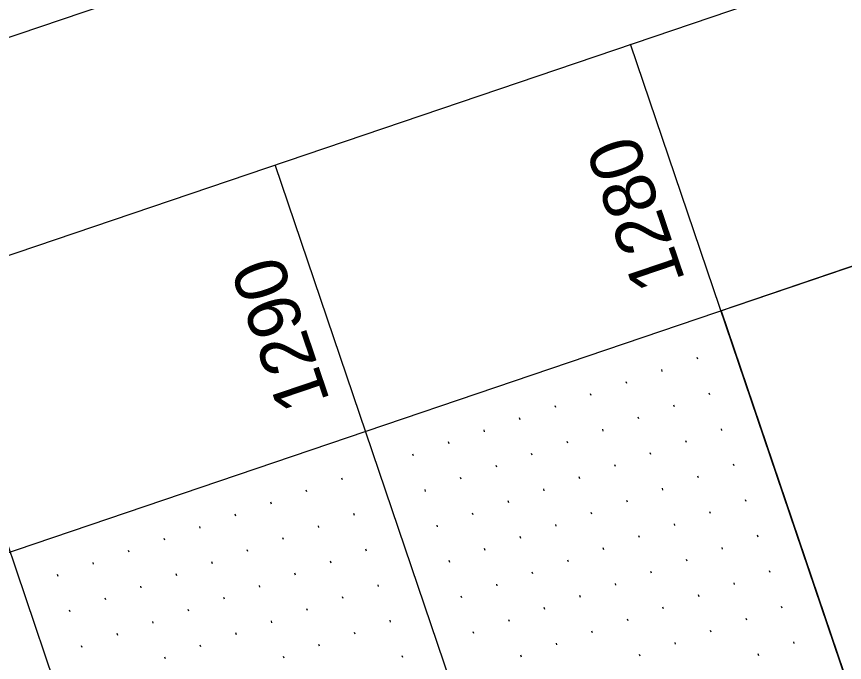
# Model space of a CAD drawing. Extents: x 2150800 to 2152547, y 141860 to 143950.
# Drawn here: x 2151679 to 2151789.3, y 143760 to 143846.1 of the extents above; entities that cross this region are included whole.
import ezdxf

# ---------------------------------------------------------------- set-up
doc = ezdxf.new("R2010")
doc.units = 0
for name, color, linetype in [('SHT_Plan_Profile_Sheet_Elev_Txt', 7, 'Continuous'), ('SHT_Plot_Shape_Half', 7, 'Continuous'), ('SHT_Profile_Grid_Major', 7, 'Continuous'), ('SHT_Profile_Grid_Minor', 7, 'Continuous'), ('SHT_Sheet_Border', 7, 'Continuous')]:
    doc.layers.add(name, color=color, linetype=linetype)

msp = doc.modelspace()

# ---------------------------------------------------------------- linework, layer by layer
at = {"layer": 'SHT_Plot_Shape_Half'}
msp.add_lwpolyline([(2151391.39, 141950.92), (2150845.24, 143560.8), (2151886.93, 143914.19), (2152433.08, 142304.31)], close=True, dxfattribs=at)
at = {"layer": 'SHT_Profile_Grid_Major'}
for p, q in [((2152266.81, 142350.86), (2151760.82, 143842.37)), ((2152219.46, 142334.8), (2151713.47, 143826.31)), ((2152172.11, 142318.73), (2151666.12, 143810.24))]:
    msp.add_line(p, q, dxfattribs=at)
at = {"layer": 'SHT_Profile_Grid_Minor'}
for p, q in [((2151769.78, 143800.4), (2151769.7, 143800.63)), ((2151765.04, 143798.79), (2151764.96, 143799.03)), ((2151760.31, 143797.18), (2151760.23, 143797.42)), ((2151755.57, 143795.58), (2151755.49, 143795.81)), ((2151771.39, 143795.66), (2151771.3, 143795.9)), ((2151750.84, 143793.97), (2151750.76, 143794.21)), ((2151766.65, 143794.06), (2151766.57, 143794.29)), ((2151746.1, 143792.36), (2151746.02, 143792.6)), ((2151761.92, 143792.45), (2151761.83, 143792.69)), ((2151741.37, 143790.76), (2151741.29, 143791)), ((2151757.18, 143790.84), (2151757.1, 143791.08)), ((2151772.99, 143790.93), (2151772.91, 143791.16)), ((2151768.26, 143789.32), (2151768.18, 143789.56)), ((2151736.63, 143789.15), (2151736.55, 143789.39)), ((2151752.45, 143789.24), (2151752.37, 143789.47)), ((2151731.9, 143787.55), (2151731.82, 143787.78)), ((2151747.71, 143787.63), (2151747.63, 143787.87)), ((2151763.52, 143787.71), (2151763.44, 143787.95)), ((2151742.98, 143786.02), (2151742.9, 143786.26)), ((2151758.79, 143786.11), (2151758.71, 143786.34)), ((2151774.6, 143786.19), (2151774.52, 143786.43)), ((2151722.43, 143784.33), (2151722.35, 143784.57)), ((2151738.24, 143784.42), (2151738.16, 143784.65)), ((2151754.05, 143784.5), (2151753.97, 143784.74)), ((2151769.86, 143784.59), (2151769.78, 143784.82)), ((2151717.69, 143782.73), (2151717.61, 143782.96)), ((2151733.51, 143782.81), (2151733.43, 143783.05)), ((2151749.32, 143782.9), (2151749.24, 143783.13)), ((2151765.13, 143782.98), (2151765.05, 143783.22)), ((2151712.96, 143781.12), (2151712.88, 143781.36)), ((2151744.58, 143781.29), (2151744.5, 143781.53)), ((2151760.39, 143781.37), (2151760.31, 143781.61)), ((2151776.2, 143781.46), (2151776.12, 143781.69)), ((2151708.22, 143779.51), (2151708.14, 143779.75)), ((2151724.04, 143779.6), (2151723.96, 143779.84)), ((2151739.85, 143779.68), (2151739.77, 143779.92)), ((2151755.66, 143779.77), (2151755.58, 143780)), ((2151771.47, 143779.85), (2151771.39, 143780.09)), ((2151766.73, 143778.24), (2151766.65, 143778.48)), ((2151703.49, 143777.91), (2151703.41, 143778.14)), ((2151719.3, 143777.99), (2151719.22, 143778.23)), ((2151735.11, 143778.08), (2151735.03, 143778.31)), ((2151750.92, 143778.16), (2151750.84, 143778.4)), ((2151698.75, 143776.3), (2151698.67, 143776.54)), ((2151714.57, 143776.39), (2151714.49, 143776.62)), ((2151746.19, 143776.55), (2151746.11, 143776.79)), ((2151762, 143776.64), (2151761.92, 143776.87)), ((2151777.81, 143776.72), (2151777.73, 143776.96)), ((2151741.45, 143774.95), (2151741.37, 143775.18)), ((2151757.26, 143775.03), (2151757.18, 143775.27)), ((2151773.08, 143775.12), (2151773, 143775.35)), ((2151694.02, 143774.7), (2151693.94, 143774.93)), ((2151709.83, 143774.78), (2151709.75, 143775.02)), ((2151725.64, 143774.86), (2151725.56, 143775.1)), ((2151689.28, 143773.09), (2151689.2, 143773.33)), ((2151705.1, 143773.17), (2151705.02, 143773.41)), ((2151720.91, 143773.26), (2151720.83, 143773.49)), ((2151736.72, 143773.34), (2151736.64, 143773.58)), ((2151752.53, 143773.43), (2151752.45, 143773.66)), ((2151768.34, 143773.51), (2151768.26, 143773.75)), ((2151716.17, 143771.65), (2151716.09, 143771.89)), ((2151747.79, 143771.82), (2151747.71, 143772.06)), ((2151763.61, 143771.9), (2151763.53, 143772.14)), ((2151779.42, 143771.99), (2151779.34, 143772.22)), ((2151684.55, 143771.48), (2151684.47, 143771.72)), ((2151700.36, 143771.57), (2151700.28, 143771.8)), ((2151695.63, 143769.96), (2151695.55, 143770.2)), ((2151711.44, 143770.04), (2151711.36, 143770.28)), ((2151727.25, 143770.13), (2151727.17, 143770.37)), ((2151743.06, 143770.21), (2151742.98, 143770.45)), ((2151758.87, 143770.3), (2151758.79, 143770.53)), ((2151774.68, 143770.38), (2151774.6, 143770.62)), ((2151690.89, 143768.35), (2151690.81, 143768.59)), ((2151706.7, 143768.44), (2151706.62, 143768.67)), ((2151722.51, 143768.52), (2151722.43, 143768.76)), ((2151738.32, 143768.61), (2151738.24, 143768.84)), ((2151754.14, 143768.69), (2151754.06, 143768.93)), ((2151769.95, 143768.77), (2151769.87, 143769.01)), ((2151781.02, 143767.25), (2151780.94, 143767.49)), ((2151686.16, 143766.75), (2151686.08, 143766.98)), ((2151701.97, 143766.83), (2151701.89, 143767.07)), ((2151717.78, 143766.92), (2151717.7, 143767.15)), ((2151749.4, 143767.08), (2151749.32, 143767.32)), ((2151765.21, 143767.17), (2151765.13, 143767.4)), ((2151697.23, 143765.23), (2151697.15, 143765.46)), ((2151713.04, 143765.31), (2151712.96, 143765.55)), ((2151728.85, 143765.39), (2151728.77, 143765.63)), ((2151744.67, 143765.48), (2151744.59, 143765.71)), ((2151760.48, 143765.56), (2151760.4, 143765.8)), ((2151776.29, 143765.65), (2151776.21, 143765.88)), ((2151755.74, 143763.96), (2151755.66, 143764.19)), ((2151771.55, 143764.04), (2151771.47, 143764.28)), ((2151692.5, 143763.62), (2151692.42, 143763.86)), ((2151708.31, 143763.7), (2151708.23, 143763.94)), ((2151724.12, 143763.79), (2151724.04, 143764.02)), ((2151739.93, 143763.87), (2151739.85, 143764.11)), ((2151687.76, 143762.01), (2151687.68, 143762.25)), ((2151703.57, 143762.1), (2151703.49, 143762.33)), ((2151719.38, 143762.18), (2151719.3, 143762.42)), ((2151751.01, 143762.35), (2151750.93, 143762.59)), ((2151766.82, 143762.43), (2151766.74, 143762.67)), ((2151782.63, 143762.52), (2151782.55, 143762.75)), ((2151730.46, 143760.66), (2151730.38, 143760.9)), ((2151746.27, 143760.74), (2151746.19, 143760.98)), ((2151762.08, 143760.83), (2151762, 143761.06)), ((2151777.89, 143760.91), (2151777.81, 143761.15)), ((2151698.84, 143760.49), (2151698.76, 143760.73)), ((2151714.65, 143760.57), (2151714.57, 143760.81))]:
    msp.add_line(p, q, dxfattribs=at)
at = {"layer": 'SHT_Sheet_Border'}
msp.add_line((2151843.89, 143830.95), (2151394.07, 143678.35), dxfattribs=at)
for points in [[(2151383.74, 142051.28), (2150877.75, 143542.79), (2151872.09, 143880.12), (2152378.08, 142388.61)], [(2151821.06, 143664.81), (2151840, 143671.23), (2151791.81, 143813.28), (2151772.87, 143806.86)]]:
    msp.add_lwpolyline(points, close=True, dxfattribs=at)

# ---------------------------------------------------------------- texts
at = {"layer": 'SHT_Plan_Profile_Sheet_Elev_Txt'}
for s, p in [('1280', (2151768.14, 143810.95)), ('1290', (2151720.8, 143794.89))]:
    msp.add_text(s, height=7, rotation=108.7393, dxfattribs=at).set_placement(p)

doc.saveas('drawing.dxf')
